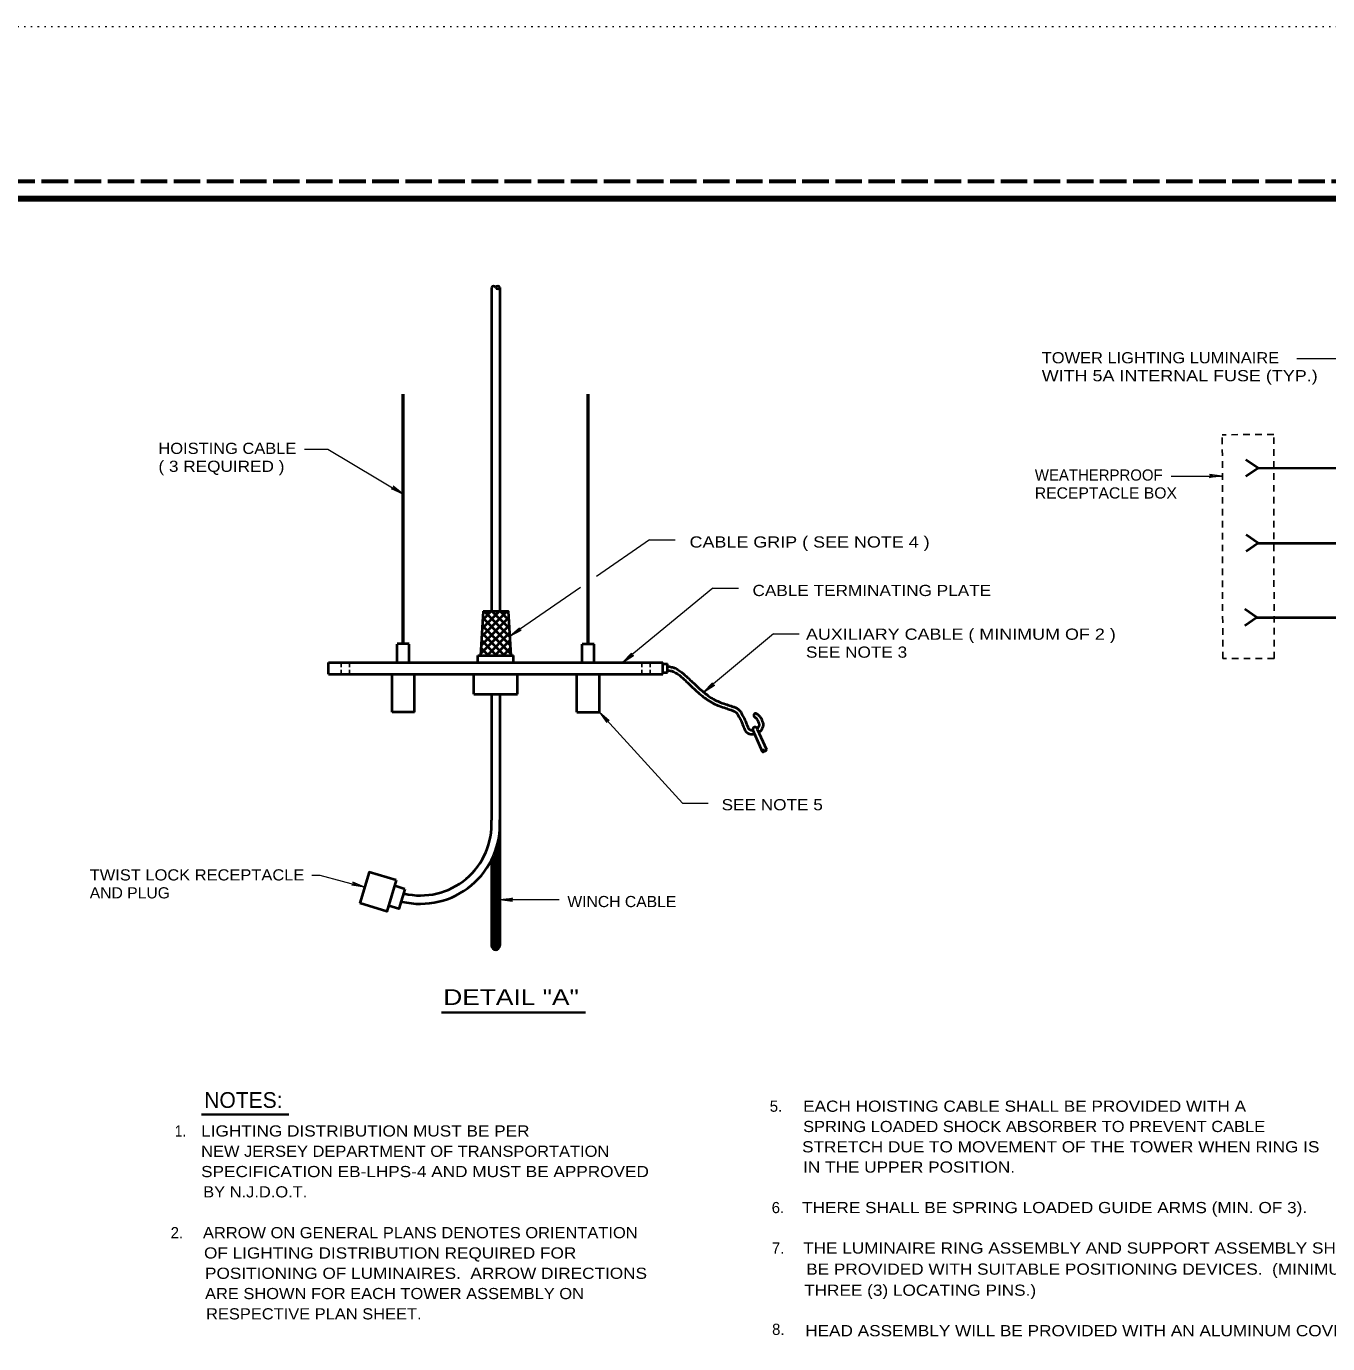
# Model space of a CAD drawing. Extents: x 312583 to 312854, y 144419 to 144597.
# Drawn here: x 312686.9 to 312775.4, y 144507.2 to 144596.8 of the extents above; entities that cross this region are included whole.
import ezdxf
from ezdxf.enums import TextEntityAlignment as Align

# ---------------------------------------------------------------- set-up
doc = ezdxf.new("R2010")
doc.units = 0
doc.header["$LTSCALE"] = 0.3
for name, pattern in [('DOTTED', [1.5, 0.3, -1.2]), ('LONG_DASHED', [7.5, 6, -1.5]), ('SHORT_DASHED', [2.7, 1.5, -1.2])]:
    doc.linetypes.add(name, pattern=pattern)
for name, color, linetype, lineweight in [('1', 7, 'Continuous', 40), ('2', 7, 'Continuous', 13), ('62', 7, 'DOTTED', 13), ('63', 7, 'LONG_DASHED', 60)]:
    doc.layers.add(name, color=color, linetype=linetype, lineweight=lineweight)

msp = doc.modelspace()

# ---------------------------------------------------------------- linework, layer by layer
at = {"layer": '1'}
for p, q in [((312718.5597, 144579.0267), (312718.5597, 144557.0157)), ((312719.127, 144579.0267), (312719.127, 144557.0157)), ((312770.7003, 144566.749), (312769.88, 144567.3163)), ((312770.7003, 144566.749), (312769.88, 144566.1816)), ((312770.7003, 144566.749), (312794.9653, 144566.8026)), ((312770.708, 144561.6353), (312769.8876, 144562.2026)), ((312770.708, 144561.6353), (312769.8876, 144561.068)), ((312770.708, 144561.6353), (312794.8963, 144561.689)), ((312717.9847, 144557.0157), (312717.8083, 144554.0103)), ((312717.8467, 144554.6927), (312719.725, 144556.571)), ((312717.885, 144555.2677), (312719.633, 144557.0157)), ((312717.9157, 144555.835), (312719.0963, 144557.0157)), ((312717.9463, 144556.4177), (312718.5443, 144557.0157)), ((312719.84, 144554.6927), (312717.9617, 144556.571)), ((312719.8017, 144555.2677), (312718.0537, 144557.0157)), ((312719.771, 144555.835), (312718.5903, 144557.0157)), ((312719.7403, 144556.4177), (312719.1423, 144557.0157)), ((312770.616, 144556.5983), (312769.7956, 144557.1656)), ((312770.616, 144556.5983), (312769.7956, 144556.031)), ((312770.616, 144556.5983), (312794.8963, 144556.5446)), ((312717.816, 144554.11), (312719.7557, 144556.0497)), ((312719.4337, 144554.0103), (312717.9003, 144555.5437)), ((312719.8707, 144554.11), (312717.931, 144556.0497)), ((312718.253, 144554.0103), (312719.7863, 144555.5437)), ((312712.963, 144554.7923), (312712.1503, 144554.7923)), ((312712.1503, 144553.5273), (312712.1503, 144554.777)), ((312712.963, 144553.5273), (312712.963, 144554.777)), ((312718.897, 144554.0103), (312717.8697, 144555.0377)), ((312718.7897, 144554.0103), (312719.817, 144555.0377)), ((312724.7237, 144554.7923), (312725.5363, 144554.7923)), ((312724.7237, 144553.5273), (312724.7237, 144554.777)), ((312725.5363, 144553.5273), (312725.5363, 144554.777)), ((312717.6243, 144554.0103), (312720.0623, 144554.0103)), ((312717.6243, 144553.5273), (312717.6243, 144554.0103)), ((312718.345, 144554.0103), (312717.839, 144554.5163)), ((312719.3417, 144554.0103), (312719.8477, 144554.5163)), ((312720.0623, 144553.5273), (312720.0623, 144554.0103)), ((312707.466, 144553.5197), (312730.2207, 144553.5273)), ((312707.466, 144552.73), (312707.466, 144553.5197)), ((312711.79, 144550.154), (312711.79, 144552.753)), ((312725.8967, 144550.154), (312725.8967, 144552.753)), ((312730.2207, 144552.7377), (312730.2207, 144553.5273)), ((312730.2207, 144553.4277), (312730.535, 144553.4277)), ((312730.2207, 144552.845), (312730.535, 144552.845)), ((312730.535, 144552.845), (312730.535, 144553.4277)), ((312707.466, 144552.73), (312730.2207, 144552.7377)), ((312713.3233, 144550.154), (312713.3233, 144552.7147)), ((312717.3637, 144551.373), (312717.3637, 144552.7377)), ((312720.323, 144551.373), (312720.323, 144552.7377)), ((312724.3633, 144550.154), (312724.3633, 144552.7147)), ((312717.3637, 144551.373), (312720.323, 144551.373)), ((312718.5597, 144551.373), (312718.5597, 144542.8017)), ((312719.127, 144551.373), (312719.127, 144542.8017)), ((312713.3233, 144550.154), (312711.79, 144550.154)), ((312724.3633, 144550.154), (312725.8967, 144550.154)), ((312736.331, 144548.9273), (312736.9673, 144547.4783)), ((312736.6377, 144549.004), (312737.2587, 144547.6087)), ((312719.127, 144542.8017), (312719.127, 144534.2763)), ((312719.0197, 144541.4293), (312719.0197, 144534.054)), ((312718.667, 144540.333), (312718.667, 144534.054)), ((312718.7513, 144540.54), (312718.7513, 144534.008)), ((312718.8433, 144540.7853), (312718.8433, 144533.9927)), ((312718.9277, 144541.0537), (312718.9277, 144534.008)), ((312718.5597, 144540.1107), (312718.5597, 144534.2763)), ((312712.6717, 144538.125), (312711.9893, 144538.3397))]:
    msp.add_line(p, q, dxfattribs=at)
at = {"layer": '1', "lineweight": 53}
for p, q in [((312712.5567, 144554.777), (312712.5567, 144571.7817)), ((312725.13, 144554.777), (312725.13, 144571.7817))]:
    msp.add_line(p, q, dxfattribs=at)
at = {"layer": '1', "linetype": 'SHORT_DASHED', "lineweight": 25}
for p, q in [((312768.3006, 144553.8), (312768.27, 144569.0183)), ((312771.7966, 144553.8076), (312768.3006, 144553.8))]:
    msp.add_line(p, q, dxfattribs=at)
at = {"layer": '1', "lineweight": 25}
for p, q in [((312708.3247, 144553.213), (312708.3247, 144553.5197)), ((312708.3247, 144552.73), (312708.3247, 144553.029)), ((312708.9073, 144553.213), (312708.9073, 144553.5197)), ((312708.9073, 144552.7607), (312708.9073, 144553.029)), ((312728.7793, 144553.213), (312728.7793, 144553.5197)), ((312728.7793, 144552.7607), (312728.7793, 144553.029)), ((312729.362, 144553.213), (312729.362, 144553.5197)), ((312729.362, 144552.73), (312729.362, 144553.029))]:
    msp.add_line(p, q, dxfattribs=at)
at = {"layer": '1', "lineweight": 158}
msp.add_lwpolyline([(312616.5, 144423.1446), (312616.5, 144585.0846), (312849, 144585.0846)], dxfattribs=at)
at = {"layer": '1', "linetype": 'SHORT_DASHED', "lineweight": 25}
msp.add_lwpolyline([(312771.7966, 144553.8076), (312771.766, 144569.026), (312768.27, 144569.0183)], dxfattribs=at)
at = {"layer": '1'}
for points in [[(312717.9847, 144557.0157), (312719.702, 144557.0157), (312719.8783, 144554.0103)], [(312712.0813, 144538.723), (312710.2413, 144539.2827), (312709.5897, 144537.159)], [(312712.0813, 144538.723), (312711.4297, 144536.5993), (312709.5897, 144537.159)], [(312712.6717, 144538.125), (312712.25, 144536.768), (312711.5677, 144536.975)]]:
    msp.add_lwpolyline(points, dxfattribs=at)
for centre, radius, start, end in [((312718.7015, 144578.9634), 0.1553, 24.03429, 155.96571), ((312718.9852, 144578.9634), 0.1553, 24.03429, 155.96571), ((312718.9852, 144579.0899), 0.1553, 204.03429, 335.96571), ((312736.5265, 144549.9317), 0.1322, 60.46122, 240.46122), ((312736.4831, 144548.975), 0.1612, 11.89086, 199.43899), ((312737.0526, 144547.4865), 0.0857, 45.21047, 185.48188), ((312737.0277, 144547.5391), 0.0857, 225.21047, 5.48188), ((312737.1734, 144547.6005), 0.0857, 225.21047, 5.48188), ((312713.7179, 144542.5373), 5.4163, 256.70257, 3.12582), ((312713.7179, 144542.5373), 4.8489, 256.70257, 3.12582), ((312718.8433, 144534.2763), 0.2837, 180, 0)]:
    msp.add_arc(centre, radius, start, end, dxfattribs=at)
for points in [[(312730.535, 144553.2667), (312730.8033, 144553.2207), (312731.0487, 144553.1363), (312731.6237, 144552.753), (312732.3137, 144552.1167), (312733.042, 144551.465), (312733.3563, 144551.2273), (312733.778, 144550.9743), (312734.146, 144550.8133), (312734.5753, 144550.6677), (312734.9357, 144550.545), (312735.1503, 144550.4607), (312735.342, 144550.3533), (312735.5107, 144550.1693), (312735.618, 144549.9547), (312735.7713, 144549.671), (312735.8787, 144549.4103), (312735.9477, 144549.2417), (312736.0397, 144549.05), (312736.262, 144548.9197), (312736.331, 144548.9197)], [(312730.535, 144553.006), (312730.742, 144552.9677), (312730.9337, 144552.9063), (312731.4627, 144552.5537), (312732.1373, 144551.925), (312732.881, 144551.2657), (312733.2107, 144551.0127), (312733.663, 144550.7443), (312734.054, 144550.5757), (312734.491, 144550.4223), (312734.8437, 144550.3073), (312735.043, 144550.2307), (312735.181, 144550.1463), (312735.296, 144550.0237), (312735.388, 144549.8397), (312735.5413, 144549.5637), (312735.641, 144549.3107), (312735.71, 144549.1343), (312735.8403, 144548.866), (312736.193, 144548.659), (312736.4613, 144548.659)], [(312736.6453, 144549.027), (312736.7067, 144549.0883), (312736.768, 144549.211), (312736.791, 144549.326), (312736.7527, 144549.4333), (312736.7067, 144549.5483), (312736.63, 144549.6633), (312736.5687, 144549.7323), (312736.4613, 144549.8167)], [(312736.745, 144548.774), (312736.9137, 144548.935), (312737.0133, 144549.1267), (312737.0593, 144549.349), (312736.9903, 144549.5253), (312736.9367, 144549.671), (312736.837, 144549.8243), (312736.745, 144549.924), (312736.5917, 144550.0467)]]:
    msp.add_spline(points, degree=3, dxfattribs=at)
at = {"layer": '2'}
for p, q in [((312773.33, 144574.201), (312776.918, 144574.201)), ((312764.7816, 144566.2046), (312768.27, 144566.2046)), ((312767.4036, 144566.312), (312767.6796, 144566.2046)), ((312768.27, 144566.2046), (312767.4036, 144566.312)), ((312767.4036, 144566.0973), (312767.6796, 144566.2046)), ((312768.27, 144566.2046), (312767.4036, 144566.0973)), ((312711.7593, 144565.3263), (312712.0507, 144565.2727)), ((312712.5567, 144564.9737), (312711.7593, 144565.3263)), ((312711.8667, 144565.5103), (312712.0507, 144565.2727)), ((312712.5567, 144564.9737), (312711.8667, 144565.5103)), ((312729.316, 144561.861), (312725.6973, 144559.3693)), ((312729.316, 144561.861), (312731.0487, 144561.861)), ((312724.601, 144558.618), (312719.8017, 144555.3137)), ((312733.6247, 144558.572), (312727.476, 144553.5273)), ((312733.6247, 144558.572), (312735.3573, 144558.572)), ((312719.8017, 144555.3137), (312720.4533, 144555.8963)), ((312719.8017, 144555.3137), (312720.576, 144555.72)), ((312720.4533, 144555.8963), (312720.2847, 144555.651)), ((312720.576, 144555.72), (312720.2847, 144555.651)), ((312737.7493, 144555.467), (312732.9883, 144551.5033)), ((312737.7493, 144555.467), (312739.482, 144555.467)), ((312727.476, 144553.5273), (312728.074, 144554.156)), ((312727.476, 144553.5273), (312728.212, 144553.995)), ((312728.074, 144554.156), (312727.936, 144553.903)), ((312728.212, 144553.995), (312727.936, 144553.903)), ((312732.9883, 144551.5033), (312733.5863, 144552.1397)), ((312732.9883, 144551.5033), (312733.7243, 144551.9787)), ((312733.5863, 144552.1397), (312733.4407, 144551.879)), ((312733.7243, 144551.9787), (312733.4407, 144551.879)), ((312725.8967, 144550.154), (312726.4027, 144549.441)), ((312725.8967, 144550.154), (312726.5637, 144549.5867)), ((312726.4027, 144549.441), (312726.2953, 144549.717)), ((312726.5637, 144549.5867), (312726.2953, 144549.717)), ((312709.0607, 144538.378), (312709.3597, 144538.4163)), ((312709.1143, 144538.5927), (312709.3597, 144538.4163)), ((312709.927, 144538.263), (312709.1143, 144538.5927)), ((312709.927, 144538.263), (312709.0607, 144538.378)), ((312719.127, 144537.4043), (312719.9933, 144537.5117)), ((312719.127, 144537.4043), (312723.1597, 144537.4043)), ((312719.127, 144537.4043), (312719.9933, 144537.297)), ((312719.9933, 144537.5117), (312719.7173, 144537.4043)), ((312719.9933, 144537.297), (312719.7173, 144537.4043))]:
    msp.add_line(p, q, dxfattribs=at)
at = {"layer": '2', "lineweight": 35}
for p, q in [((312715.1483, 144529.721), (312724.9571, 144529.721)), ((312698.8257, 144522.8042), (312704.7597, 144522.8042))]:
    msp.add_line(p, q, dxfattribs=at)
at = {"layer": '2'}
for points in [[(312705.833, 144568.025), (312707.4277, 144568.025), (312712.5567, 144564.9737)], [(312725.8967, 144550.154), (312731.5547, 144543.967), (312733.2873, 144543.967)], [(312706.3337, 144539.068), (312706.891, 144539.068), (312709.927, 144538.263)]]:
    msp.add_lwpolyline(points, dxfattribs=at)
at = {"layer": '62'}
msp.add_line((312601.2, 144596.7846), (312853.5, 144596.7846), dxfattribs=at)
at = {"layer": '63'}
msp.add_line((312851.75, 144586.2246), (312583.526, 144586.2246), dxfattribs=at)

# ---------------------------------------------------------------- texts
at = {"layer": '2'}
for s, width, p in [('TOWER LIGHTING LUMINAIRE', 1.1, (312755.9891, 144573.8703)), ('WITH 5A INTERNAL FUSE (TYP.)', 1.2, (312755.9891, 144572.6503)), ('HOISTING CABLE', 1.1, (312695.9008, 144567.7097)), ('( 3 REQUIRED )', 1.15, (312695.9008, 144566.4897)), ('RECEPTACLE BOX', 1.05, (312755.5186, 144564.677)), ('CABLE GRIP ( SEE NOTE 4 )', 1.2, (312732.0308, 144561.3433)), ('CABLE TERMINATING PLATE', 1.15, (312736.3122, 144558.0466)), ('AUXILIARY CABLE ( MINIMUM OF 2 )', 1.2, (312739.9497, 144555.075)), ('SEE NOTE 3', 1.15, (312739.9497, 144553.855)), ('SEE NOTE 5', 1.15, (312734.2115, 144543.48)), ('TWIST LOCK RECEPTACLE', 1.1, (312691.2273, 144538.7067)), ('AND PLUG', 1.05, (312691.2273, 144537.4867)), ('WINCH CABLE', 1.05, (312723.7193, 144536.8944)), ('EACH HOISTING CABLE SHALL BE PROVIDED WITH A', 1.15, (312739.7555, 144522.979)), ('SPRING LOADED SHOCK ABSORBER TO PREVENT CABLE', 1.1, (312739.7554, 144521.599)), ('LIGHTING DISTRIBUTION MUST BE PER', 1.15, (312698.8062, 144521.295)), ('NEW JERSEY DEPARTMENT OF TRANSPORTATION', 1.1, (312698.8062, 144519.915)), ('STRETCH DUE TO MOVEMENT OF THE TOWER WHEN RING IS', 1.15, (312739.6856, 144520.219)), ('IN THE UPPER POSITION.', 1.15, (312739.7552, 144518.839)), ('SPECIFICATION EB-LHPS-4 AND MUST BE APPROVED', 1.15, (312698.8062, 144518.535)), ('BY N.J.D.O.T.', 1.1, (312698.9462, 144517.155)), ('THERE SHALL BE SPRING LOADED GUIDE ARMS (MIN. OF 3).', 1.15, (312739.6853, 144516.0866)), ('ARROW ON GENERAL PLANS DENOTES ORIENTATION', 1.1, (312698.9308, 144514.3796)), ('OF LIGHTING DISTRIBUTION REQUIRED FOR', 1.15, (312699.0009, 144512.9996)), ('THE LUMINAIRE RING ASSEMBLY AND SUPPORT ASSEMBLY SHALL', 1.15, (312739.7554, 144513.3343)), ('BE PROVIDED WITH SUITABLE POSITIONING DEVICES.  (MINIMUM OF', 1.15, (312739.9657, 144511.9006)), ('POSITIONING OF LUMINAIRES.  ARROW DIRECTIONS', 1.15, (312699.071, 144511.6196)), ('ARE SHOWN FOR EACH TOWER ASSEMBLY ON', 1.1, (312699.0709, 144510.2396)), ('THREE (3) LOCATING PINS.)', 1.15, (312739.8255, 144510.467)), ('RESPECTIVE PLAN SHEET.', 1.1, (312699.141, 144508.8596)), ('HEAD ASSEMBLY WILL BE PROVIDED WITH AN ALUMINUM COVER.', 1.15, (312739.8956, 144507.7146))]:
    msp.add_text(s, height=0.76, dxfattribs=dict(at, width=width)).set_placement(p)
msp.add_text('WEATHERPROOF', height=0.76, dxfattribs=at).set_placement((312755.5186, 144565.897))
for s, height, width, p in [('DETAIL "A"', 1.07, 1.25, (312719.8889, 144530.242)), ('1.', 0.76, 0.9, (312697.3997, 144521.295))]:
    msp.add_text(s, height=height, dxfattribs=dict(at, width=width)).set_placement(p, align=Align.CENTER)
for s, height, p in [('NOTES:', 1.07, (312701.6788, 144523.2442)), ('5.', 0.76, (312737.9103, 144522.979)), ('6.', 0.76, (312738.0415, 144516.0866)), ('2.', 0.76, (312697.1558, 144514.3796)), ('7.', 0.76, (312738.0542, 144513.3343)), ('8.', 0.76, (312738.0685, 144507.8066))]:
    msp.add_text(s, height=height, dxfattribs=at).set_placement(p, align=Align.CENTER)

doc.saveas('drawing.dxf')
